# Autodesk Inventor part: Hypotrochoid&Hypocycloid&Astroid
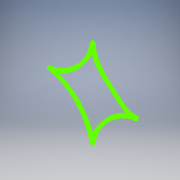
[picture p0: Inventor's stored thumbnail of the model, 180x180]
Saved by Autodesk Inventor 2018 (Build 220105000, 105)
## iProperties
Created: 2008-02
Part Number: Hypotrochoid&Hypocycloid&Astroid
Document SubType Name: Modeling
Designer: Autodesk, Inc.
Density: 1 g/cm^3
Material: Generic
Appearance: Default
Author: Autodesk, Inc.
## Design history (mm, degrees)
sketch "Sketch1"
  geometry: 300 further points
  constraints: 300 other
